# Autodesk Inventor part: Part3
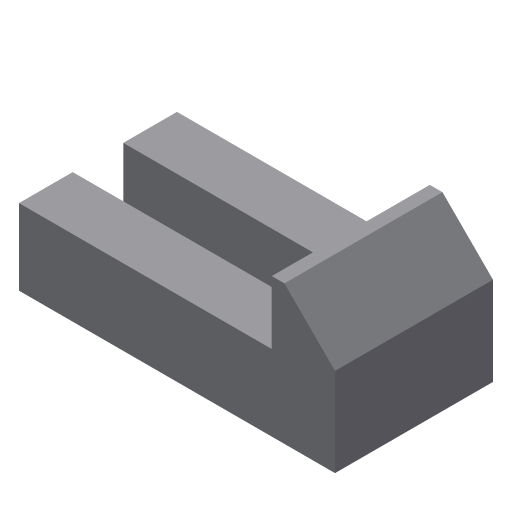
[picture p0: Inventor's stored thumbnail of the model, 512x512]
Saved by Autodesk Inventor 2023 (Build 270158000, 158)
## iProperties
Created: 2002-01
Part Number: Part3
Document SubType Name: Modeling
Designer: ***
Density: 1 g/cm^3
Material: Generic
Appearance: Default
Control State: 0
Master: False
Checked Out: False
Shininess: 77.0
Length Units: 11269
Angle Units: 11279
Time Units: 11290
Mass Units: 11283
Length Display Precision: 3
Angle Display Precision: 2
Density: 0.0
Volumn: 0.0
Area: 0.0
PropertySet Name: Model Information
Author: ***
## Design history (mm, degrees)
sketch "Sketch2"
  geometry: L1 (23.289, -5.477)-(-16.711, -5.477); L2 (-16.711, -5.477)-(-16.711, 4.523); L3 (-16.711, 4.523)-(-18.711, 4.523); L4 (-18.711, 4.523)-(-26.711, -3.477); L5 (-26.711, -3.477)-(-26.711, -17.477); L6 (-26.711, -17.477)-(23.289, -17.477); L7 (23.289, -17.477)-(23.289, -5.477)
  constraints: 14 end point, 4 parallel, 1 horizontal, 1 perpendicular
  dimensions: "d0" = 50 distance of L5.end L6.end; "d1" = 12 distance of L6.end L1.start; "d2" = 22 distance between parallel lines of L3 L6; "d3" = 135 deg angle of L5 L4; "d4" = 2 distance of L2.end L3.end; "d5" = 40 distance of L1.start L1.end
extrude "Extrusion1" new body sketch "Sketch2" stored distance "d6" = 25; taper "d7" = 0 deg
sketch "Sketch3"
  geometry: L1 (-4, -8.5)-(36, -8.5); L2 (36, -8.5)-(36, -16.5); L3 (36, -16.5)-(-4, -16.5); L4 (-4, -16.5)-(-4, -8.5); L5 (40, -25)-(40, 0) reference; L6 (40, 0)-(0, 0) reference
  constraints: 8 end point, 2 parallel, 1 horizontal, 1 perpendicular
  dimensions: "d8" = 8 distance of L1.end L2.end; "d9" = 40 distance of L1.start L1.end; "d10" = 4 distance between parallel lines of L5 L2; "d11" = 8.5 distance between parallel lines of L6 L1
extrude "Extrusion2" cut sketch "Sketch3" extent not by distance; stored distance "d12" = 25; taper "d13" = 0 deg
body "Solid1"
